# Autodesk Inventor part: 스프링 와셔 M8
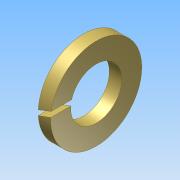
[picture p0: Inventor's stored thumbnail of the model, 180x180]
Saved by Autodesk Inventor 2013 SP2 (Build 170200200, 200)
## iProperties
Created: 2025-07
Part Number: 스프링 와셔 M8
Material: Generic
Document SubType Name: Modeling
Designer: a
Density: 1 g/cm^3
Author: a
변환 표준: STEP AP214IS
전처리기: Build: 200, Release: 2013 SP2 Update 6 - Date: Thu 07/17/2014
전송 단위: 밀리미터
불확실성: 0.01
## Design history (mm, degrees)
node "스프링 와셔 M81"
body "Solid1"
node "기준1"
